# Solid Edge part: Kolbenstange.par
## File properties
Username: bmolnar
Dokumentum tartalom típus: 0
Author: bmolnar
Last saved by: bmolnar
Revision: 82
Sűrűség: 0,000 kg/m^3
Pontosság: 0,990
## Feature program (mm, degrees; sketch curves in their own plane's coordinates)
base feature "unnamed BaseFeature 1"
sketch for "unnamed Protrusion 1" plane through (23.3, 0, 0) normal (1, 0, 0) x-axis (0, -1, 0)
  circle centre (0, 0) radius 10
extrude "unnamed Protrusion 1" add finite 6.7 along +normal
sketch for "Furat_1" plane through (-20, 0, 0) normal (-1, 0, 0) x-axis (0, 1, 0)
hole "Furat_1" diameter 6 finite  VBottomAngle = 118 deg; ThreadDepth = 15 mm
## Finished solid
Body 1: solid body, 14 faces, 20 edges, 8 vertices.
  Faces by surface: plane 7, cylinder 4, cone 2, torus 1
  Edges by curve: circle 10, line 6, ellipse 2, intersection 2
Bounding box of the edges (mm; curved faces can reach further): 50.000 x 20.000 x 20.000, from (-20, -10, -10) to (30, 10, 10).
Cylindrical faces by radius (mm): R2.4585 x2, R5 x1, R10 x1
Conical faces (half-angle, radius in mm at the cone's reference point): 45 deg R2.8085 x1, 59 deg R2.4585 x1
Toroidal faces (ring radius, tube radius in mm): R3.8 r1.2 x1
Planar faces by outward normal: +x 1, +z 1, -x 2, -z 1, oblique 2
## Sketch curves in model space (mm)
circle centre (23.3, 0, 0) radius 10
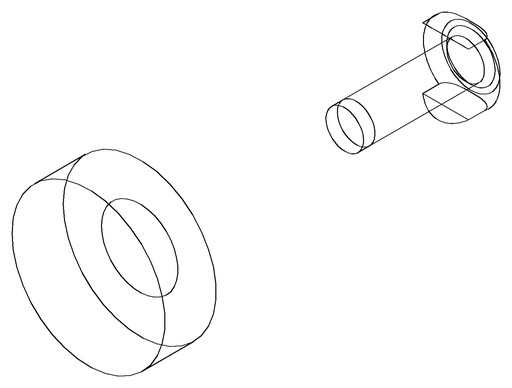
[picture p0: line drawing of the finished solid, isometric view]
